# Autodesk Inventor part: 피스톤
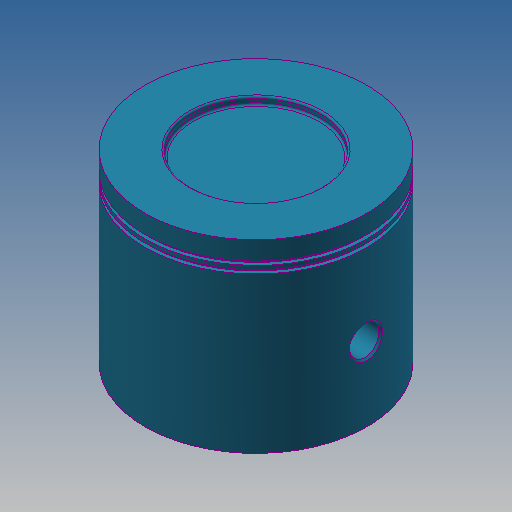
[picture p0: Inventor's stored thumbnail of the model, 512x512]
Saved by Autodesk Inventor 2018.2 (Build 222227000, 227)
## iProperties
Created: 2016-11
Part Number: 피스톤
Material: 강철, 탄소
Document SubType Name: Modeling
Designer: mduedu
Density: 7.87 g/cm^3
Mass: 410.128 g
Surface Area: 237.507 cm^2
Volume: 52.1129 cm^3
Appearance: 터키옥색
Author: mduedu
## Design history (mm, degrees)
sketch "스케치1"
  geometry: C1 r 30 at (0, 0); 1 further point
  constraints: 1 centre point, 1 coincident
  dimensions: "d0" = 60 diameter of C1
extrude "돌출1" new body sketch "스케치1" distance "d1" = 50; taper "d2" = 0 deg
sketch "스케치2"
  geometry: C1 r 28 at (0, 0); 1 further point
  constraints: 1 centre point, 1 coincident
  dimensions: "d3" = 56 diameter of C1
extrude "돌출2" cut sketch "스케치2" distance "d4" = 45; taper "d5" = 0 deg
sketch "스케치3"
  geometry: L1 (30, 0)-(30, 50) reference; L2 (30, 45)-(29, 45); L3 (29, 45)-(29, 44); L4 (29, 44)-(30, 44); L5 (30, 44)-(30, 45); L6 (30, 43)-(29, 43); L7 (29, 43)-(29, 42); L8 (29, 42)-(30, 42); L9 (30, 42)-(30, 43); L10 (30, 50)-(-30, 50) reference; L11 (0, 50)-(0, 0)
  constraints: 18 end point, 4 parallel, 3 equal length, 3 perpendicular, 2 horizontal, 2 point on line, 1 midpoint
  dimensions: "d6" = 1 distance of L2.start L2.end; "d8" = 5 distance between parallel lines of L10 L2; "d9" = 1 distance between parallel lines of L6 L4
revolve "회전1" sketch "스케치3" stored, may be unused: angle "d10" = 90 deg
node "작업 평면1"
sketch "스케치4"
  geometry: L1 (0, -22.978)-(45, -22.978) reference; L2 (45, -22.978)-(45, 22.978) reference; L3 (45, 22.978)-(0, 22.978) reference; L4 (0, 22.978)-(0, 25.377) reference; L5 (0, 25.377)-(42, 25.377) reference; L6 (42, 25.377)-(42, 24.187) reference; L7 (42, 24.187)-(43, 24.187) reference; L8 (43, 24.187)-(43, 25.377) reference; L9 (43, 25.377)-(44, 25.377) reference; L10 (44, 25.377)-(44, 24.187) reference; L11 (44, 24.187)-(45, 24.187) reference; L12 (45, 24.187)-(45, 25.377) reference; L13 (45, 25.377)-(50, 25.377) reference; L14 (50, 25.377)-(50, -25.377) reference; L15 (50, -25.377)-(45, -25.377) reference; L16 (45, -25.377)-(45, -24.187) reference; L17 (45, -24.187)-(44, -24.187) reference; L18 (44, -24.187)-(44, -25.377) reference; L19 (44, -25.377)-(43, -25.377) reference; L20 (43, -25.377)-(43, -24.187) reference; L21 (43, -24.187)-(42, -24.187) reference; L22 (42, -24.187)-(42, -25.377) reference; L23 (42, -25.377)-(0, -25.377) reference; L24 (0, -25.377)-(0, -22.978) reference; L25 (12.5, 22.978)-(45, 22.978); L26 (45, 22.978)-(45, -22.978); L27 (45, -22.978)-(12.5, -22.978); L28 (12.5, -22.978)-(12.5, 22.978); C1 r 7.5 at (20, 0); C2 r 4 at (20, 0); 1 further point
  constraints: 8 end point, 2 centre point, 2 parallel, 1 coincident, 1 horizontal, 1 horizontal alignment, 1 perpendicular, 1 point on line, 1 tangent
  dimensions: "d12" = 15 diameter of C1; "d13" = 8 diameter of C2; "d14" = 20 distance of point (0, 0) C1.centre
  node "절단 모서리 투영1"
extrude "돌출3" join sketch "스케치4" stored distance "d15" = 11.75; taper "d16" = 0 deg
extrude "돌출4" cut sketch "스케치4" extent not by distance; stored distance "d17" = 72; taper "d18" = 0 deg
fillet "모깎기2" dims "d20" = 3
chamfer "모따기1" distance "d21" = 0.5; stored, may be unused: second distance "d22" = 2, angle "d23" = 45 deg
chamfer "모따기2" distance "d24" = 0.5; stored, may be unused: second distance "d25" = 2, angle "d26" = 45 deg
sketch "스케치5"
  geometry: C1 r 17.5 at (0, 0); 1 further point
  constraints: 1 centre point, 1 coincident
  dimensions: "d27" = 35 diameter of C1
extrude "돌출5" cut sketch "스케치5" distance "d28" = 2; taper "d29" = 0 deg
fillet "모깎기3" dims "d30" = 0.5
node "솔리드1"
mirror "대칭1"
other parameters: "d11" = -16
